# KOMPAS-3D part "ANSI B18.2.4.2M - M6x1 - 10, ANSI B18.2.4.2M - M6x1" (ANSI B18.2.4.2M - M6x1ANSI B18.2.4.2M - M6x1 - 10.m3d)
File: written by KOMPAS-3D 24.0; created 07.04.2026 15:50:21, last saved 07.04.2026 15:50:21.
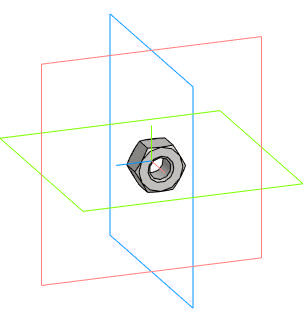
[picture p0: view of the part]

Document properties: Автор: Main; Полное имя файла: D:\DN.ru Аутсерс\Стекло смотровое DN.ru\Исходники\Стекло смотровое DN.ru SG2-34G-F тип В ГОСТ 21836-2021 Ду25 Ру40, углеродистая сталь, фланцевое\ANSI B18.2.4.2M - M6x1ANSI B18.2.4.2M - M6x1 - 10.m3d

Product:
- Body: Solid1  | qty 1
- Part/product: ANSI B18.2.4.2M - M6x1 - 10  | designation ANSI B18.2.4.2M - M6x1
    Комментарий: Типы метрических   шестигранных гаек   2
    additional columns: Сталь, мягкая

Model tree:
1. Solid1  (labels: Solid1)

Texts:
  ANSI B18.2.4.2M - M6x1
